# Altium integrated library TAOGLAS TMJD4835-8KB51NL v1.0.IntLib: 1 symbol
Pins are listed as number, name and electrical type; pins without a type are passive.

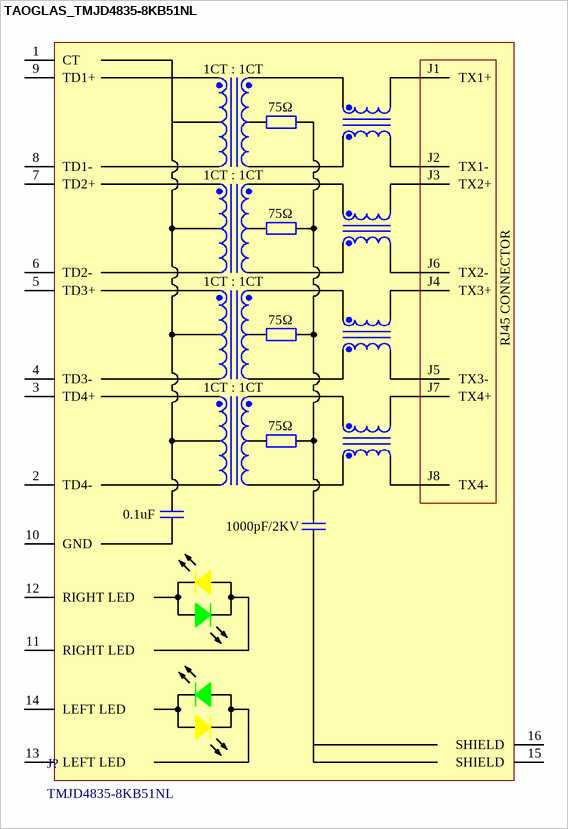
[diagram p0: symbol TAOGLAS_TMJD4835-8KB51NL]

## TAOGLAS_TMJD4835-8KB51NL
designator J?, comment TMJD4835-8KB51NL
RJ45 connector with integrated magnetics 1G Base-T Vertical with THT mount and LED (Green/Yellow, Yellow/Green); ComponentLibStatus: Created; MFG: Taoglas; Temp_High: +85C; Temp_Low: -40C
footprint TAOGLAS_TMJD4835-8KB51NL (RJ45 connector with integrated magnetics 1G Base-T Vertical with THT mount and LED (Green/Yellow, Yellow/Green))
pins: 1 CT, 2 TD4-, 3 TD4+, 4 TD3-, 5 TD3+, 6 TD2-, 7 TD2+, 8 TD1-, 9 TD1+, 10 GND, 11 RIGHT LED, 12 RIGHT LED, 13 LEFT LED, 14 LEFT LED, 15 SHIELD, 16 SHIELD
